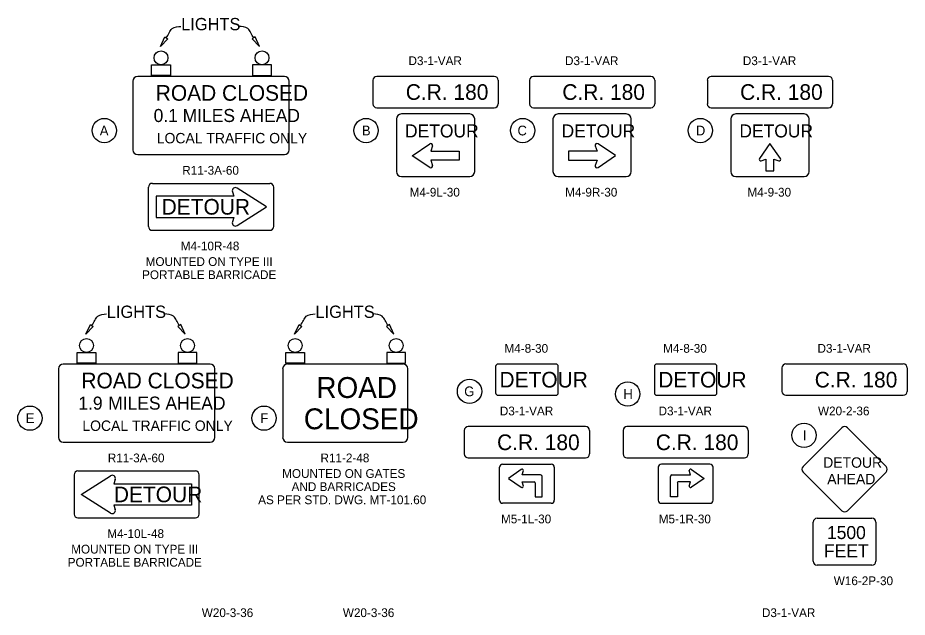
# Model space of a CAD drawing. Extents: x 1633.3 to 1707.6, y 1081.5 to 1106.
# Drawn here: x 1691.69 to 1705.89, y 1096.33 to 1105.9 of the extents above; entities that cross this region are included whole.
import ezdxf

# ---------------------------------------------------------------- set-up
doc = ezdxf.new("R2010")
doc.units = 0
for name, color, linetype in [('SH_Text', 7, 'Continuous'), ('SN_P_Signs', 7, 'Continuous'), ('SN_P_Text', 7, 'Continuous')]:
    doc.layers.add(name, color=color, linetype=linetype)

msp = doc.modelspace()

# ---------------------------------------------------------------- linework, layer by layer
at = {"layer": 'SH_Text'}
for centre in [(1693.071, 1104.1), (1697.251, 1104.1), (1699.751, 1104.1), (1702.59, 1104.1), (1698.903, 1099.934), (1701.43, 1099.892), (1691.882, 1099.506), (1695.622, 1099.506), (1704.245, 1099.232)]:
    msp.add_circle(centre, 0.194, dxfattribs=at)
at = {"layer": 'SN_P_Signs'}
for p, q in [((1697.986, 1103.698), (1698.267, 1103.889)), ((1698.31, 1103.856), (1698.283, 1103.771)), ((1700.912, 1103.856), (1700.939, 1103.771)), ((1701.236, 1103.699), (1700.955, 1103.889)), ((1703.701, 1103.895), (1703.533, 1103.656)), ((1703.869, 1103.656), (1703.701, 1103.895)), ((1698.267, 1103.508), (1697.986, 1103.698)), ((1698.283, 1103.771), (1698.736, 1103.771)), ((1698.736, 1103.771), (1698.736, 1103.625)), ((1700.939, 1103.771), (1700.486, 1103.771)), ((1700.486, 1103.771), (1700.486, 1103.625)), ((1700.955, 1103.508), (1701.236, 1103.699)), ((1698.736, 1103.625), (1698.283, 1103.625)), ((1698.283, 1103.625), (1698.31, 1103.54)), ((1700.486, 1103.625), (1700.939, 1103.625)), ((1700.939, 1103.625), (1700.912, 1103.54)), ((1703.561, 1103.618), (1703.637, 1103.643)), ((1703.637, 1103.643), (1703.637, 1103.642)), ((1703.637, 1103.642), (1703.637, 1103.457)), ((1703.764, 1103.643), (1703.841, 1103.618)), ((1703.637, 1103.457), (1703.764, 1103.457)), ((1695.118, 1103.122), (1695.14, 1103.053)), ((1695.661, 1102.881), (1695.192, 1103.18)), ((1695.14, 1103.053), (1693.9, 1103.053)), ((1693.9, 1103.053), (1693.9, 1102.709)), ((1695.192, 1102.582), (1695.661, 1102.881)), ((1693.9, 1102.709), (1695.14, 1102.709)), ((1695.14, 1102.709), (1695.118, 1102.64)), ((1699.382, 1098.196), (1699.382, 1098.721)), ((1699.432, 1098.771), (1700.207, 1098.771)), ((1700.257, 1098.721), (1700.257, 1098.196)), ((1701.917, 1098.721), (1701.917, 1098.196)), ((1702.742, 1098.771), (1701.967, 1098.771)), ((1702.792, 1098.196), (1702.792, 1098.721)), ((1692.702, 1098.287), (1693.17, 1098.586)), ((1699.727, 1098.684), (1699.523, 1098.545)), ((1699.523, 1098.545), (1699.727, 1098.405)), ((1699.742, 1098.599), (1699.763, 1098.67)), ((1700.039, 1098.599), (1699.742, 1098.599)), ((1700.039, 1098.599), (1700.039, 1098.599)), ((1700.062, 1098.248), (1700.062, 1098.576)), ((1702.112, 1098.248), (1702.112, 1098.576)), ((1702.136, 1098.599), (1702.433, 1098.599)), ((1702.136, 1098.599), (1702.136, 1098.599)), ((1702.433, 1098.599), (1702.412, 1098.67)), ((1702.448, 1098.684), (1702.652, 1098.545)), ((1702.652, 1098.545), (1702.448, 1098.405)), ((1693.245, 1098.529), (1693.223, 1098.459)), ((1693.223, 1098.459), (1694.462, 1098.459)), ((1694.462, 1098.459), (1694.462, 1098.115)), ((1699.763, 1098.42), (1699.742, 1098.49)), ((1699.742, 1098.49), (1699.937, 1098.49)), ((1699.953, 1098.474), (1699.953, 1098.248)), ((1702.222, 1098.474), (1702.222, 1098.248)), ((1702.433, 1098.49), (1702.237, 1098.49)), ((1702.412, 1098.42), (1702.433, 1098.49)), ((1693.17, 1097.989), (1692.702, 1098.287)), ((1700.207, 1098.146), (1699.432, 1098.146)), ((1699.953, 1098.248), (1700.062, 1098.248)), ((1699.953, 1098.248), (1700.062, 1098.248)), ((1701.967, 1098.146), (1702.742, 1098.146)), ((1702.222, 1098.248), (1702.112, 1098.248)), ((1694.462, 1098.115), (1693.223, 1098.115)), ((1693.223, 1098.115), (1693.245, 1098.046))]:
    msp.add_line(p, q, dxfattribs=at)
for points in [[(1694.084, 1105.564), (1693.966, 1105.44), (1694.037, 1105.595)], [(1695.433, 1105.564), (1695.55, 1105.44), (1695.48, 1105.595)], [(1693.826, 1104.978), (1693.826, 1105.151), (1694.125, 1105.151), (1694.125, 1104.978)], [(1695.738, 1104.978), (1695.738, 1105.151), (1695.439, 1105.151), (1695.439, 1104.978)], [(1692.895, 1100.97), (1692.778, 1100.847), (1692.849, 1101.001)], [(1694.245, 1100.97), (1694.362, 1100.847), (1694.291, 1101.001)], [(1696.227, 1100.97), (1696.11, 1100.847), (1696.181, 1101.001)], [(1697.577, 1100.97), (1697.694, 1100.847), (1697.623, 1101.001)], [(1692.638, 1100.385), (1692.638, 1100.557), (1692.937, 1100.557), (1692.937, 1100.385)], [(1694.55, 1100.385), (1694.55, 1100.557), (1694.251, 1100.557), (1694.251, 1100.385)], [(1695.97, 1100.385), (1695.97, 1100.557), (1696.269, 1100.557), (1696.269, 1100.385)], [(1697.882, 1100.385), (1697.882, 1100.557), (1697.583, 1100.557), (1697.583, 1100.385)]]:
    msp.add_lwpolyline(points, close=True, dxfattribs=at)
for points in [[(1695.947, 1104.965), (1693.604, 1104.965)], [(1699.298, 1104.965), (1697.423, 1104.965)], [(1701.799, 1104.965), (1699.924, 1104.965)], [(1704.638, 1104.965), (1702.763, 1104.965)], [(1693.525, 1104.887), (1693.525, 1103.793)], [(1696.025, 1103.793), (1696.025, 1104.887)], [(1697.361, 1104.902), (1697.361, 1104.527)], [(1699.361, 1104.902), (1699.361, 1104.527)], [(1699.861, 1104.902), (1699.861, 1104.527)], [(1701.861, 1104.902), (1701.861, 1104.527)], [(1702.701, 1104.902), (1702.701, 1104.527)], [(1704.701, 1104.902), (1704.701, 1104.527)], [(1697.423, 1104.465), (1699.298, 1104.465)], [(1699.924, 1104.465), (1701.799, 1104.465)], [(1702.763, 1104.465), (1704.638, 1104.465)], [(1697.736, 1104.285), (1697.736, 1103.445)], [(1698.906, 1104.365), (1697.816, 1104.365)], [(1698.986, 1103.445), (1698.986, 1104.285)], [(1700.236, 1104.285), (1700.236, 1103.445)], [(1701.406, 1104.365), (1700.316, 1104.365)], [(1701.486, 1103.445), (1701.486, 1104.285)], [(1703.076, 1104.285), (1703.076, 1103.445)], [(1704.246, 1104.365), (1703.156, 1104.365)], [(1704.326, 1103.445), (1704.326, 1104.285)], [(1693.604, 1103.715), (1695.947, 1103.715)], [(1703.764, 1103.457), (1703.764, 1103.642)], [(1693.838, 1103.256), (1695.713, 1103.256)], [(1697.816, 1103.365), (1698.906, 1103.365)], [(1700.316, 1103.365), (1701.406, 1103.365)], [(1703.156, 1103.365), (1704.246, 1103.365)], [(1693.775, 1102.569), (1693.775, 1103.194)], [(1695.775, 1103.194), (1695.775, 1102.569)], [(1695.713, 1102.506), (1693.838, 1102.506)], [(1692.337, 1100.293), (1692.337, 1099.199)], [(1694.759, 1100.371), (1692.415, 1100.371)], [(1694.837, 1099.199), (1694.837, 1100.293)], [(1695.919, 1100.293), (1695.919, 1099.199)], [(1697.841, 1100.371), (1695.997, 1100.371)], [(1697.919, 1099.199), (1697.919, 1100.293)], [(1699.32, 1100.331), (1699.32, 1099.911)], [(1700.28, 1100.371), (1699.36, 1100.371)], [(1700.32, 1099.911), (1700.32, 1100.331)], [(1701.855, 1100.331), (1701.855, 1099.911)], [(1702.815, 1100.371), (1701.895, 1100.371)], [(1702.855, 1099.911), (1702.855, 1100.331)], [(1703.893, 1100.309), (1703.893, 1099.934)], [(1705.83, 1100.371), (1703.955, 1100.371)], [(1705.893, 1100.309), (1705.893, 1099.934)], [(1699.36, 1099.871), (1700.28, 1099.871)], [(1701.895, 1099.871), (1702.815, 1099.871)], [(1703.955, 1099.871), (1705.83, 1099.871)], [(1698.82, 1099.309), (1698.82, 1098.934)], [(1700.757, 1099.371), (1698.882, 1099.371)], [(1700.82, 1099.309), (1700.82, 1098.934)], [(1701.355, 1099.309), (1701.355, 1098.934)], [(1703.292, 1099.371), (1701.417, 1099.371)], [(1703.355, 1099.309), (1703.355, 1098.934)], [(1704.23, 1098.734), (1704.849, 1099.353)], [(1704.937, 1099.353), (1705.556, 1098.734)], [(1692.415, 1099.121), (1694.759, 1099.121)], [(1695.997, 1099.121), (1697.841, 1099.121)], [(1698.882, 1098.871), (1700.757, 1098.871)], [(1701.417, 1098.871), (1703.292, 1098.871)], [(1692.587, 1098.6), (1692.587, 1097.975)], [(1694.525, 1098.662), (1692.65, 1098.662)], [(1694.587, 1097.975), (1694.587, 1098.6)], [(1704.849, 1098.027), (1704.23, 1098.646)], [(1705.556, 1098.646), (1704.937, 1098.027)], [(1692.65, 1097.912), (1694.525, 1097.912)], [(1704.393, 1097.221), (1704.393, 1097.846)], [(1704.455, 1097.909), (1705.33, 1097.909)], [(1705.393, 1097.846), (1705.393, 1097.221)], [(1705.33, 1097.159), (1704.455, 1097.159)]]:
    msp.add_lwpolyline(points, dxfattribs=at)
for centre in [(1693.976, 1105.262), (1695.589, 1105.262), (1692.787, 1100.668), (1694.4, 1100.668), (1696.119, 1100.668), (1697.732, 1100.668)]:
    msp.add_circle(centre, 0.111, dxfattribs=at)
for centre, radius, start, end in [((1693.604, 1104.887), 0.0781, 90, 180), ((1695.947, 1104.887), 0.0781, 0, 90), ((1697.423, 1104.902), 0.0625, 90, 180), ((1699.298, 1104.902), 0.0625, 0, 90), ((1699.924, 1104.902), 0.0625, 90, 180), ((1701.799, 1104.902), 0.0625, 0, 90), ((1702.763, 1104.902), 0.0625, 90, 180), ((1704.638, 1104.902), 0.0625, 0, 90), ((1697.423, 1104.527), 0.0625, 180, 270), ((1699.298, 1104.527), 0.0625, 270, 0), ((1699.924, 1104.527), 0.0625, 180, 270), ((1701.799, 1104.527), 0.0625, 270, 0), ((1702.763, 1104.527), 0.0625, 180, 270), ((1704.638, 1104.527), 0.0625, 270, 0), ((1697.816, 1104.285), 0.08, 90, 180), ((1698.906, 1104.285), 0.08, 0, 90), ((1700.316, 1104.285), 0.08, 90, 180), ((1701.406, 1104.285), 0.08, 0, 90), ((1703.156, 1104.285), 0.08, 90, 180), ((1704.246, 1104.285), 0.08, 0, 90), ((1698.283, 1103.865), 0.0286, 342.1992, 124.1969), ((1700.939, 1103.865), 0.0286, 55.8031, 197.8008), ((1693.604, 1103.793), 0.0781, 180, 270), ((1695.947, 1103.793), 0.0781, 270, 0), ((1698.283, 1103.532), 0.0286, 235.8031, 17.8008), ((1700.939, 1103.532), 0.0286, 162.1992, 304.1969), ((1703.553, 1103.642), 0.0246, 144.9207, 287.6378), ((1703.848, 1103.642), 0.0246, 252.3622, 35.0792), ((1697.816, 1103.445), 0.08, 180, 270), ((1698.906, 1103.445), 0.08, 270, 0), ((1700.316, 1103.445), 0.08, 180, 270), ((1701.406, 1103.445), 0.08, 270, 0), ((1703.156, 1103.445), 0.08, 180, 270), ((1704.246, 1103.445), 0.08, 270, 0), ((1693.838, 1103.194), 0.0625, 90, 180), ((1695.713, 1103.194), 0.0625, 0, 90), ((1695.165, 1103.138), 0.05, 57.4891, 197.8189), ((1693.838, 1102.569), 0.0625, 180, 270), ((1695.165, 1102.625), 0.05, 162.1811, 302.5109), ((1695.713, 1102.569), 0.0625, 270, 360), ((1692.415, 1100.293), 0.0781, 90, 180), ((1694.759, 1100.293), 0.0781, 0, 90), ((1695.997, 1100.293), 0.0783, 90, 180), ((1697.841, 1100.293), 0.0783, 0, 90), ((1699.36, 1100.331), 0.04, 90, 180), ((1700.28, 1100.331), 0.04, 0, 90), ((1701.895, 1100.331), 0.04, 90, 180), ((1702.815, 1100.331), 0.04, 0, 90), ((1703.955, 1100.309), 0.0625, 90, 180), ((1705.83, 1100.309), 0.0625, 0, 90), ((1699.36, 1099.911), 0.04, 180, 270), ((1700.28, 1099.911), 0.04, 270, 0), ((1701.895, 1099.911), 0.04, 180, 270), ((1702.815, 1099.911), 0.04, 270, 0), ((1703.955, 1099.934), 0.0625, 180, 270), ((1705.83, 1099.934), 0.0625, 270, 0), ((1698.882, 1099.309), 0.0625, 90, 180), ((1700.757, 1099.309), 0.0625, 0, 90), ((1701.417, 1099.309), 0.0625, 90, 180), ((1703.292, 1099.309), 0.0625, 0, 90), ((1704.893, 1099.309), 0.0625, 45, 135), ((1692.415, 1099.199), 0.0781, 180, 270), ((1694.759, 1099.199), 0.0781, 270, 0), ((1695.997, 1099.199), 0.0783, 180, 270), ((1697.841, 1099.199), 0.0783, 270, 0), ((1698.882, 1098.934), 0.0625, 180, 270), ((1700.757, 1098.934), 0.0625, 270, 0), ((1701.417, 1098.934), 0.0625, 180, 270), ((1703.292, 1098.934), 0.0625, 270, 0), ((1699.432, 1098.721), 0.05, 90, 180), ((1699.742, 1098.67), 0.0209, 0.0017, 134.9999), ((1700.207, 1098.721), 0.05, 0, 90), ((1701.967, 1098.721), 0.05, 90, 180), ((1702.433, 1098.67), 0.0209, 45.0001, 179.9983), ((1702.742, 1098.721), 0.05, 0, 90), ((1704.274, 1098.69), 0.0625, 135, 225), ((1705.512, 1098.69), 0.0625, 315, 45), ((1692.65, 1098.6), 0.0625, 90, 180), ((1693.197, 1098.544), 0.05, 342.1811, 122.5109), ((1694.525, 1098.6), 0.0625, 0, 90), ((1700.039, 1098.576), 0.0234, 0, 90), ((1702.136, 1098.576), 0.0234, 90, 180), ((1699.742, 1098.42), 0.0209, 225.0001, 0.0017), ((1699.937, 1098.474), 0.0156, 0, 90), ((1702.237, 1098.474), 0.0156, 90, 180), ((1702.433, 1098.42), 0.0209, 179.9983, 314.9999), ((1699.432, 1098.196), 0.05, 180, 270), ((1700.207, 1098.196), 0.05, 270, 360), ((1701.967, 1098.196), 0.05, 180, 270), ((1702.742, 1098.196), 0.05, 270, 0), ((1693.197, 1098.031), 0.05, 237.4891, 17.8189), ((1704.893, 1098.071), 0.0625, 225, 315), ((1692.65, 1097.975), 0.0625, 180, 270), ((1694.525, 1097.975), 0.0625, 270, 0), ((1704.455, 1097.846), 0.0625, 90, 180), ((1705.33, 1097.846), 0.0625, 0, 90), ((1704.455, 1097.221), 0.0625, 180, 270), ((1705.33, 1097.221), 0.0625, 270, 0)]:
    msp.add_arc(centre, radius, start, end, dxfattribs=at)
for points in [[(1694.061, 1105.579), (1694.097, 1105.633), (1694.134, 1105.759), (1694.249, 1105.762), (1694.295, 1105.764)], [(1695.456, 1105.579), (1695.42, 1105.633), (1695.383, 1105.759), (1695.268, 1105.762), (1695.222, 1105.764)], [(1692.872, 1100.986), (1692.908, 1101.039), (1692.945, 1101.165), (1693.061, 1101.168), (1693.106, 1101.17)], [(1694.268, 1100.986), (1694.232, 1101.039), (1694.195, 1101.165), (1694.08, 1101.168), (1694.034, 1101.17)], [(1696.204, 1100.986), (1696.24, 1101.039), (1696.277, 1101.165), (1696.393, 1101.168), (1696.438, 1101.17)], [(1697.6, 1100.986), (1697.564, 1101.039), (1697.527, 1101.165), (1697.411, 1101.168), (1697.366, 1101.17)]]:
    msp.add_open_spline(points, degree=3, dxfattribs=at)

# ---------------------------------------------------------------- texts
at = {"layer": 'SH_Text'}
for s, p in [('A', (1692.998, 1104.022)), ('B', (1697.184, 1104.022)), ('C', (1699.669, 1104.022)), ('D', (1702.518, 1104.022)), ('G', (1698.818, 1099.856)), ('H', (1701.36, 1099.814)), ('E', (1691.816, 1099.428)), ('F', (1695.561, 1099.428)), ('I', (1704.225, 1099.154))]:
    msp.add_text(s, height=0.156, dxfattribs=at).set_placement(p)
at = {"layer": 'SN_P_Signs'}
for s, height, p in [('LIGHTS', 0.196, (1694.298, 1105.702)), ('ROAD CLOSED', 0.25, (1693.892, 1104.576)), ('C.R. 180', 0.25, (1697.885, 1104.59)), ('C.R. 180', 0.25, (1700.385, 1104.59)), ('C.R. 180', 0.25, (1703.224, 1104.59)), ('0.1', 0.2083, (1693.858, 1104.236)), ('MILES AHEAD', 0.20833, (1694.322, 1104.236)), ('DETOUR', 0.2083, (1697.873, 1103.99)), ('DETOUR', 0.2083, (1700.373, 1103.99)), ('DETOUR', 0.2083, (1703.213, 1103.99)), ('LOCAL TRAFFIC ONLY', 0.16667, (1693.908, 1103.895)), ('DETOUR', 0.25, (1693.986, 1102.757)), ('LIGHTS', 0.196, (1693.11, 1101.108)), ('LIGHTS', 0.196, (1696.442, 1101.108)), ('DETOUR', 0.25, (1699.381, 1099.996)), ('DETOUR', 0.25, (1701.916, 1099.996)), ('C.R. 180', 0.25, (1704.416, 1099.996)), ('ROAD CLOSED', 0.25, (1692.704, 1099.982)), ('ROAD', 0.3333, (1696.457, 1099.829)), ('1.9', 0.2083, (1692.656, 1099.642)), ('MILES AHEAD', 0.20833, (1693.133, 1099.642)), ('CLOSED', 0.3333, (1696.257, 1099.329)), ('LOCAL TRAFFIC ONLY', 0.16667, (1692.72, 1099.302)), ('C.R. 180', 0.25, (1699.343, 1098.996)), ('C.R. 180', 0.25, (1701.878, 1098.996)), ('DETOUR', 0.1667, (1704.551, 1098.714)), ('AHEAD', 0.1667, (1704.616, 1098.45)), ('DETOUR', 0.25, (1693.223, 1098.163)), ('1500', 0.2083, (1704.612, 1097.575)), ('FEET', 0.2083, (1704.565, 1097.284))]:
    msp.add_text(s, height=height, dxfattribs=at).set_placement(p)
at = {"layer": 'SN_P_Text'}
for s, p in [('D3-1-VAR', (1697.928, 1105.145)), ('D3-1-VAR', (1700.428, 1105.145)), ('D3-1-VAR', (1703.268, 1105.145)), ('R11-3A-60', (1694.315, 1103.395)), ('M4-9L-30', (1697.947, 1103.045)), ('M4-9R-30', (1700.431, 1103.045)), ('M4-9-30', (1703.341, 1103.045)), ('M4-10R-48', (1694.291, 1102.186)), ('MOUNTED ON TYPE III', (1693.731, 1101.937)), ('PORTABLE BARRICADE', (1693.674, 1101.727)), ('M4-8-30', (1699.461, 1100.551)), ('M4-8-30', (1701.995, 1100.551)), ('D3-1-VAR', (1704.46, 1100.551)), ('D3-1-VAR', (1699.387, 1099.551)), ('D3-1-VAR', (1701.922, 1099.551)), ('W20-2-36', (1704.468, 1099.551)), ('R11-3A-60', (1693.126, 1098.801)), ('R11-2-48', (1696.523, 1098.801)), ('MOUNTED ON GATES', (1695.911, 1098.552)), ('AND BARRICADES ', (1696.061, 1098.342)), ('AS PER STD. DWG. MT-101.60', (1695.528, 1098.132)), ('M5-1L-30', (1699.406, 1097.826)), ('M5-1R-30', (1701.925, 1097.826)), ('M4-10L-48', (1693.119, 1097.592)), ('MOUNTED ON TYPE III', (1692.542, 1097.344)), ('PORTABLE BARRICADE', (1692.486, 1097.134)), ('W16-2P-30', (1704.72, 1096.839)), ('W20-3-36', (1694.627, 1096.329)), ('W20-3-36', (1696.88, 1096.329)), ('D3-1-VAR', (1703.573, 1096.329))]:
    msp.add_text(s, height=0.14, dxfattribs=at).set_placement(p)

doc.saveas('drawing.dxf')
